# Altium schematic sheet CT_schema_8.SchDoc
size 405 x 220 mm
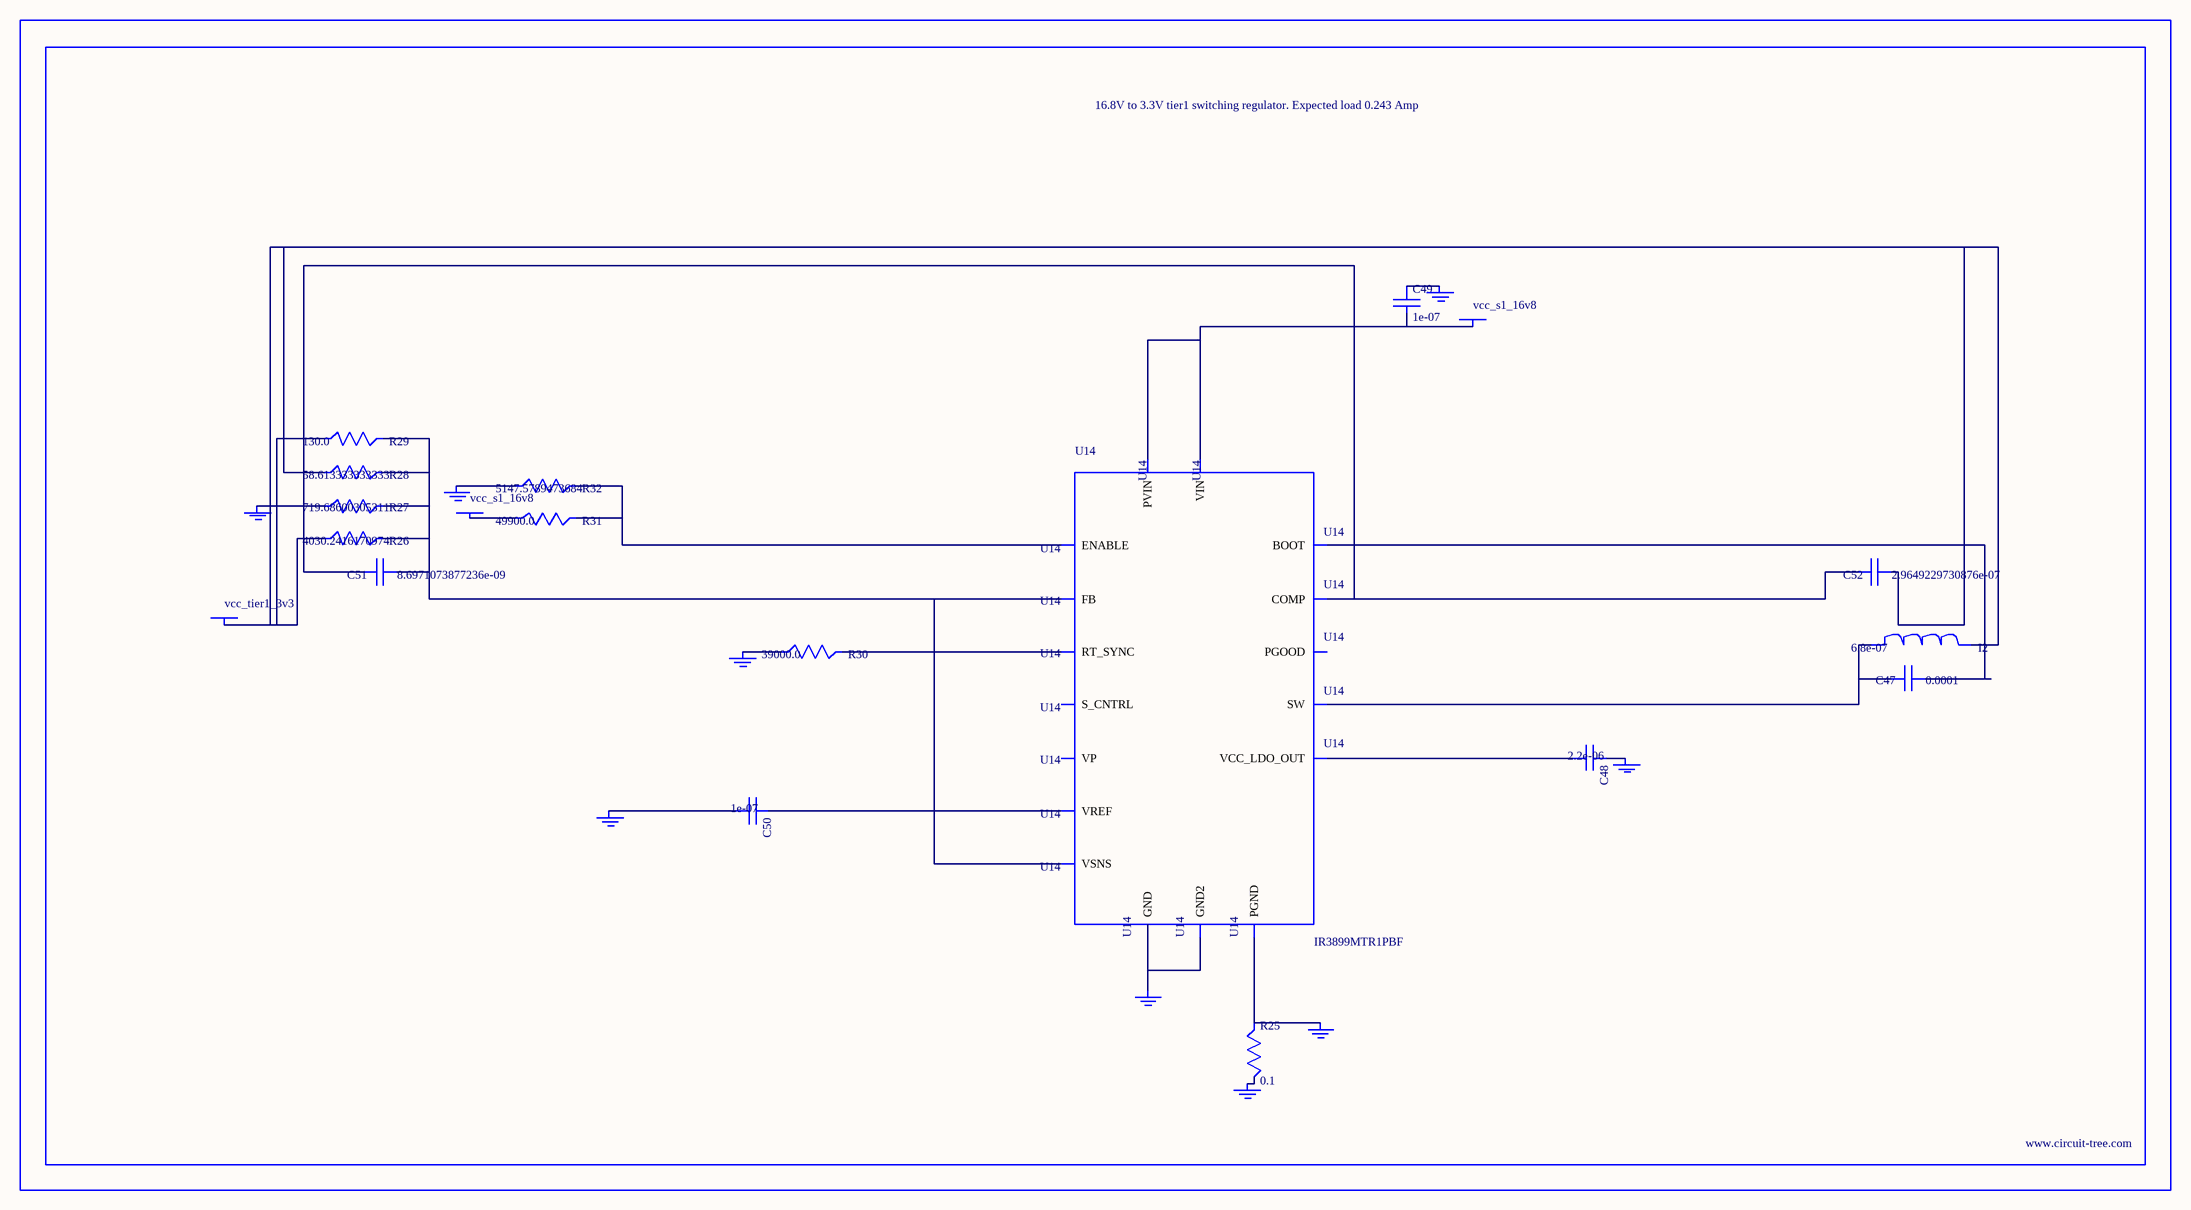
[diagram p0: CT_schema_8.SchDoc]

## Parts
BORDER7  (no value)
C47  0.0001  [C1210]
C48  2.2e-06  [C0603]
C49  1e-07  [C0402]
C50  1e-07  [C0402]
C51  8.6971073877236e-09  [R0603]
C52  2.9649229730876e-07  [R0603]
GND_INSTANCE_7_0  (no value)
GND_INSTANCE_7_1  (no value)
GND_INSTANCE_7_2  (no value)
GND_INSTANCE_7_3  (no value)
GND_INSTANCE_7_4  (no value)
GND_INSTANCE_7_5  (no value)
GND_INSTANCE_7_6  (no value)
GND_INSTANCE_7_7  (no value)
GND_INSTANCE_7_8  (no value)
I2  6.8e-07  [IND25X25CZ]
POWER_INSTANCE_7_0  vcc_s1_16v8
POWER_INSTANCE_7_1  vcc_s1_16v8
POWER_INSTANCE_7_2  vcc_tier1_3v3
R25  0.1  [R0603]
R26  4030.2416170974  [R0603]
R27  719.68600305311  [R0603]
R28  58.613333333333  [R0603]
R29  130.0  [R0603]
R30  39000.0  [R0603]
R31  49900.0  [R0603]
R32  5147.5789473684  [R0603]
U14  IR3899MTR1PBF  [IR3899MTR1PBF]

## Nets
NetC47_1: C47.1 U14.14(BOOT)
NetC47_2: C47.2 I2.1 U14.12(SW)
NetC48_1: C48.1 GND_INSTANCE_7_4.0(GND)
NetC48_2: C48.2 U14.10(VCC_LDO_OUT)
NetC49_1: C49.1 GND_INSTANCE_7_3.0(GND)
NetC49_2: C49.2 POWER_INSTANCE_7_0.0(PWR) U14.9(VIN) U14.13(PVIN)
NetC50_1: C50.1 U14.2(VREF)
NetC50_2: C50.2 GND_INSTANCE_7_1.0(GND)
NetC51_1: C51.1 R26.2 R27.2 R28.2 R29.2 U14.1(FB) U14.8(VSNS)
NetC51_2: C51.2 C52.2 U14.3(COMP)
NetC52_1: C52.1 I2.2 POWER_INSTANCE_7_2.0(PWR) R26.1 R28.1 R29.1
NetGND_INSTANCE_7_0_0: GND_INSTANCE_7_0.0(GND) R27.1
NetGND_INSTANCE_7_2_0: GND_INSTANCE_7_2.0(GND) R30.1
NetGND_INSTANCE_7_5_0: GND_INSTANCE_7_5.0(GND) R25.2
NetGND_INSTANCE_7_6_0: GND_INSTANCE_7_6.0(GND) R25.1 U14.11(PGND)
NetGND_INSTANCE_7_7_0: GND_INSTANCE_7_7.0(GND) R32.1
NetGND_INSTANCE_7_8_0: GND_INSTANCE_7_8.0(GND) U14.4(GND) U14.17(GND2)
NetPOWER_INSTANCE_7_1_0: POWER_INSTANCE_7_1.0(PWR) R31.1
NetR30_2: R30.2 U14.5(RT_SYNC)
NetR31_2: R31.2 R32.2 U14.15(ENABLE)

Not connected (* = marked no-connect by the designer): U14 6(S_CNTRL) 7(PGOOD) 16(VP)

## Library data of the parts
BORDER7 = BORDER_PAGE7
C47 = GRM32ER61A107ME20L
C48 = C0603C225K8RACTU
C49 C50 = C0402C104K3RACTU
C51 = C51
C52 = C52
GND_INSTANCE_7_0-GND_INSTANCE_7_8 = GND
I2 = IHLP2525CZERR68M01
POWER_INSTANCE_7_0-POWER_INSTANCE_7_2 = PWR
R25 = ERJ-3RSFR10V
R26 = R26
R27 = R27
R28 = R28
R29 = RC0603JR-07130RL
R30 = RC0603JR-0739KL
R31 = RC0603FR-0749K9
R32 = R32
